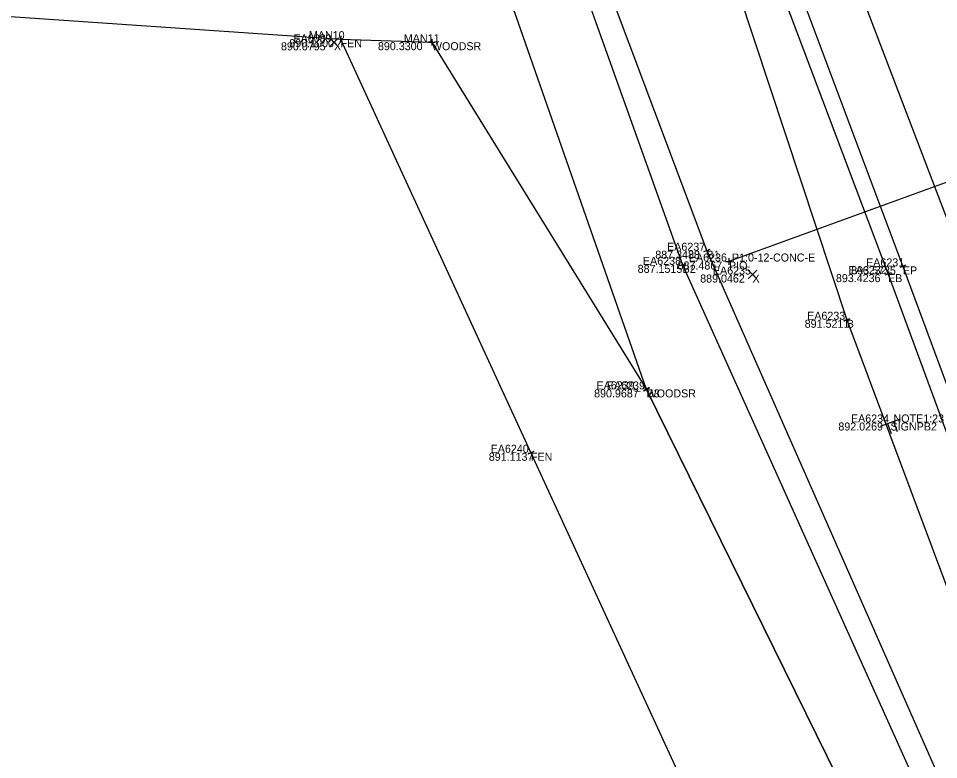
# Model space of a CAD drawing. Extents: x 179044 to 189691, y 286531 to 301257.
# Drawn here: x 180120 to 180258, y 300401.7 to 300512.8 of the extents above; entities that cross this region are included whole.
import ezdxf

# ---------------------------------------------------------------- set-up
doc = ezdxf.new("R2010")
doc.units = 0
for name, color, linetype in [('DR_X_Elev_Flow', 7, 'Continuous'), ('DR_X_Storm_Sewer', 7, 'Continuous'), ('PM_X_Channelizing_Line', 7, 'Continuous'), ('PV_X_EOP', 7, 'Continuous'), ('PV_X_Shoulder_Aggregate', 7, 'Continuous'), ('RD_X_Fence', 7, 'Continuous'), ('SN_X_Public', 7, 'Continuous'), ('SV_X_Break_Lines', 7, 'Continuous'), ('SV_X_Random_Point', 7, 'Continuous'), ('SV_X_Shot_Marker', 7, 'Continuous'), ('SV_X_Text_Comment', 7, 'Continuous'), ('SV_X_Text_Description', 7, 'Continuous'), ('SV_X_Text_Elevation', 7, 'Continuous'), ('SV_X_Text_Name', 7, 'Continuous'), ('VG_X_Tree_Line_Lt', 7, 'Continuous')]:
    doc.layers.add(name, color=color, linetype=linetype)

msp = doc.modelspace()

# ---------------------------------------------------------------- linework, layer by layer
at = {"layer": 'DR_X_Elev_Flow'}
for p, q in [((180226.57, 300476.89), (180226.57, 300475.89)), ((180226.07, 300476.39), (180227.07, 300476.39)), ((180226.54, 300476.39), (180226.59, 300476.39)), ((180226.57, 300476.42), (180226.57, 300476.37)), ((180226.57, 300476.39), (180226.57, 300476.39)), ((180226.57, 300476.39), (180226.57, 300476.39))]:
    msp.add_line(p, q, dxfattribs=at)
at = {"layer": 'DR_X_Storm_Sewer'}
msp.add_line((180300.7, 300503.37), (180226.57, 300476.39), dxfattribs=at)
at = {"layer": 'PM_X_Channelizing_Line'}
msp.add_lwpolyline([(180190.45, 300582.5), (180201.74, 300580.9), (180210.8, 300577.93), (180219.1, 300571.65), (180228.24, 300559.5), (180237.94, 300538.54), (180264.92, 300467.92), (180293.4, 300391.71), (180324.64, 300308.04), (180350.47, 300238.9)], dxfattribs=at)
at = {"layer": 'PV_X_EOP'}
msp.add_lwpolyline([(179371.15, 300578.05), (179477.17, 300579.53), (179563.01, 300579.45), (179660.63, 300579.91), (179772.35, 300580.84), (179883.3, 300581.22), (179986.95, 300581.66), (180080.46, 300581.62), (180131.14, 300581.88), (180152.42, 300580.9), (180177.37, 300581.24), (180192.48, 300580.81), (180205.12, 300578.92), (180211.9, 300576.37), (180217.06, 300570.92), (180226.26, 300546.03), (180252.64, 300475.66), (180284.89, 300388.78), (180312.05, 300315.75), (180342, 300235.31)], dxfattribs=at)
at = {"layer": 'PV_X_Shoulder_Aggregate'}
msp.add_lwpolyline([(179563.45, 300578.23), (179660.98, 300578.02), (179772.75, 300578.9), (179883.7, 300579.45), (179986.9, 300579.72), (180080.26, 300579.65), (180131.52, 300579.63), (180152.89, 300578.4), (180177.17, 300578.87), (180192.85, 300577.82), (180203.73, 300575.4), (180212.87, 300569.27), (180224.05, 300544.43), (180250.42, 300474.5), (180282.67, 300386.99), (180309.92, 300313.99), (180339.84, 300234.33)], dxfattribs=at)
at = {"layer": 'RD_X_Fence'}
msp.add_lwpolyline([(179565.42, 300550.82), (179667.83, 300544.25), (179812.22, 300533.93), (179896.21, 300528.36), (179941.19, 300525.4), (180078.77, 300515.9), (180168.34, 300509.72), (180196.88, 300447.72), (180266.67, 300296.15), (180285.87, 300252.94)], dxfattribs=at)
at = {"layer": 'SN_X_Public'}
for p, q in [((180249.3, 300451.7), (180252.29, 300452.82)), ((180250.34, 300452.09), (180250.9, 300450.59)), ((180250.79, 300452.26), (180250.79, 300452.26)), ((180251.24, 300452.42), (180251.8, 300450.93))]:
    msp.add_line(p, q, dxfattribs=at)
at = {"layer": 'SV_X_Break_Lines'}
for points in [[(180320.9, 300212.18), (180282.07, 300307.44), (180254.03, 300376.29), (180214.22, 300457.22), (180192.83, 300518.47), (180187, 300524.65), (180178.54, 300551.92), (180167.49, 300556.19), (180133.43, 300560.27), (180078.67, 300564.71), (179988.56, 300564.71), (179881.16, 300565.14), (179774.57, 300564.41), (179665.2, 300563.79), (179565.53, 300563.69)], [(180193.08, 300550.15), (180219.62, 300475.89), (180264.74, 300375.59), (180291.67, 300310.22), (180324.83, 300229.15)], [(180195.86, 300550.95), (180223.23, 300478.01), (180267.79, 300377.03), (180294.71, 300311.68), (180328.37, 300228.86)], [(180221.04, 300537.77), (180244.23, 300467.66), (180276.38, 300381.79), (180302.55, 300313.64), (180332.87, 300230.92)]]:
    msp.add_lwpolyline(points, dxfattribs=at)
at = {"layer": 'SV_X_Random_Point'}
for p, q in [((180166.68, 300508.58), (180168.01, 300509.92)), ((180166.68, 300509.92), (180168.01, 300508.58)), ((180229.43, 300473.78), (180230.77, 300475.11)), ((180229.43, 300475.11), (180230.77, 300473.78))]:
    msp.add_line(p, q, dxfattribs=at)
at = {"layer": 'SV_X_Shot_Marker'}
for p, q in [((180167.84, 300509.75), (180168.84, 300509.68)), ((180168.37, 300510.22), (180168.3, 300509.22)), ((180182.04, 300509.77), (180182.01, 300508.77)), ((180168.34, 300509.72), (180168.34, 300509.72)), ((180181.53, 300509.28), (180182.53, 300509.25)), ((180182.03, 300509.27), (180182.03, 300509.27)), ((180223.7, 300478.19), (180222.77, 300477.84)), ((180223.06, 300478.48), (180223.41, 300477.55)), ((180223.23, 300478.01), (180223.23, 300478.01)), ((180220.09, 300476.05), (180219.15, 300475.72)), ((180219.45, 300476.36), (180219.79, 300475.42)), ((180219.62, 300475.89), (180219.62, 300475.89)), ((180253.11, 300475.84), (180252.17, 300475.49)), ((180252.46, 300476.13), (180252.82, 300475.19)), ((180252.64, 300475.66), (180252.64, 300475.66)), ((180250.89, 300474.68), (180249.95, 300474.33)), ((180250.25, 300474.97), (180250.6, 300474.04)), ((180250.42, 300474.5), (180250.42, 300474.5)), ((180244.71, 300467.82), (180243.76, 300467.5)), ((180244.08, 300468.14), (180244.39, 300467.19)), ((180244.23, 300467.66), (180244.23, 300467.66)), ((180213.77, 300457), (180214.66, 300457.45)), ((180214.64, 300457.49), (180213.79, 300456.96)), ((180213.95, 300457.65), (180214.48, 300456.8)), ((180214.44, 300456.78), (180213.99, 300457.67)), ((180214.22, 300457.22), (180214.22, 300457.22)), ((180214.22, 300457.22), (180214.22, 300457.22)), ((180197.33, 300447.93), (180196.43, 300447.51)), ((180196.67, 300448.18), (180197.09, 300447.27)), ((180196.88, 300447.72), (180196.88, 300447.72))]:
    msp.add_line(p, q, dxfattribs=at)
at = {"layer": 'VG_X_Tree_Line_Lt'}
msp.add_lwpolyline([(180168.34, 300509.72), (180182.03, 300509.27), (180214.22, 300457.22), (180254.03, 300376.29), (180282.07, 300307.44), (180320.9, 300212.18)], dxfattribs=at)

# ---------------------------------------------------------------- texts
at = {"layer": 'SV_X_Text_Comment'}
for s, height, p in [('X', 1.2, (180167.35, 300508.05)), ('FEN', 1.2, (180168.34, 300508.52)), ('WOODSR', 1.2, (180182.03, 300508.07)), ('B1', 1.2, (180223.23, 300476.81)), ('B2', 1.2, (180219.62, 300474.69)), ('P1=0-12-CONC-E', 0.06, (180226.57, 300476.33)), ('PIO', 1.2, (180226.57, 300475.19)), ('EP', 1.2, (180252.64, 300474.46)), ('X', 1.2, (180230.1, 300473.24)), ('EB', 1.2, (180250.42, 300473.3)), ('B', 1.2, (180244.23, 300466.46)), ('WOODSR', 1.2, (180214.22, 300456.02)), ('B3', 1.2, (180214.22, 300456.02)), ('SIGNPB2', 1.2, (180250.79, 300451.06)), ('FEN', 1.2, (180196.88, 300446.52))]:
    msp.add_text(s, height=height, dxfattribs=at).set_placement(p)
at = {"layer": 'SV_X_Text_Description'}
for s, height, p in [(' P1:0-12-CONC-E', 1.2, (180226.57, 300476.39)), ('P1= 0-12-CONC-E', 0.06, (180226.57, 300476.39)), (' NOTE1:23 SOUTH', 1.2, (180250.79, 300452.26))]:
    msp.add_text(s, height=height, dxfattribs=at).set_placement(p)
at = {"layer": 'SV_X_Text_Elevation'}
for s, height, p in [('890.0795', 1.2, (180159.4, 300508.05)), ('890.1000', 1.2, (180160.65, 300508.52)), ('890.3300', 1.2, (180173.94, 300508.07)), ('887.3488', 1.2, (180215.52, 300476.81)), ('887.1515', 1.2, (180212.88, 300474.69)), ('887.4867', 1.2, (180218.86, 300475.19)), ('887.49', 0.06, (180226.29, 300476.33)), ('893.5735', 1.2, (180244.9, 300474.46)), ('889.0462', 1.2, (180222.25, 300473.24)), ('893.4236', 1.2, (180242.6, 300473.3)), ('891.5211', 1.2, (180237.92, 300466.46)), ('890.9687', 1.2, (180206.35, 300456.02)), ('890.9687', 1.2, (180206.35, 300456.02)), ('892.0269', 1.2, (180242.97, 300451.06)), ('891.1137', 1.2, (180190.56, 300446.52))]:
    msp.add_text(s, height=height, dxfattribs=at).set_placement(p)
at = {"layer": 'SV_X_Text_Name'}
for s, height, p in [('EA6089', 1.2, (180161.28, 300509.25)), ('MAN10', 1.2, (180163.59, 300509.72)), ('MAN11', 1.2, (180177.82, 300509.27)), ('EA6237', 1.2, (180217.29, 300478.01)), ('EA6238', 1.2, (180213.67, 300475.89)), ('EA6236', 1.2, (180220.55, 300476.39)), ('EA6231', 1.2, (180247.13, 300475.66)), ('EA6235', 1.2, (180224.16, 300474.44)), ('EA6236', 0.06, (180226.27, 300476.39)), ('EA6232', 1.2, (180244.49, 300474.5)), ('EA6233', 1.2, (180238.29, 300467.66)), ('EA6239_1', 1.2, (180206.72, 300457.22)), ('EA6239', 1.2, (180208.26, 300457.22)), ('EA6234', 1.2, (180244.86, 300452.26)), ('EA6240', 1.2, (180190.84, 300447.72))]:
    msp.add_text(s, height=height, dxfattribs=at).set_placement(p)

doc.saveas('drawing.dxf')
